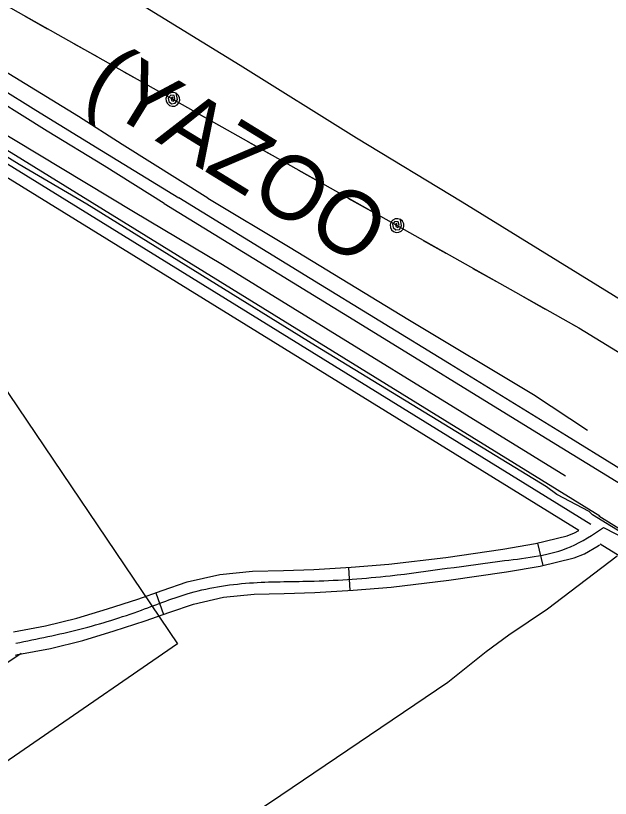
# Model space of a CAD drawing. Extents: x 3355724 to 3393621, y 594744 to 620174.
# Drawn here: x 3386643 to 3387415, y 614246 to 615262 of the extents above; entities that cross this region are included whole.
import ezdxf

# ---------------------------------------------------------------- set-up
doc = ezdxf.new("R2010")
doc.units = 0
for name, color, linetype in [('V-RAIL-IDEN', 7, 'Continuous'), ('V-RAIL-TRAK', 7, 'Continuous'), ('V-ROAD-CNTR', 7, 'Continuous'), ('V-SITE-OTLN', 7, 'Continuous'), ('V-TOPO-SHOR', 7, 'Continuous'), ('V-UTIL-LINE', 7, 'Continuous')]:
    doc.layers.add(name, color=color, linetype=linetype)

msp = doc.modelspace()

# ---------------------------------------------------------------- linework, layer by layer
at = {"layer": 'V-RAIL-TRAK'}
for points in [[(3385904.3, 615614.3), (3385937.1, 615589.8), (3385995.9, 615553.5), (3386041.4, 615526), (3386138.6, 615465.8), (3386217.5, 615417.8), (3386284.6, 615376.6), (3386346.6, 615338.2), (3386401.2, 615305), (3386480.6, 615255.4), (3386574.3, 615198.6), (3386668.9, 615139.7), (3386754.1, 615087.1), (3386854.6, 615025.9)], [(3386835.4, 615018.6), (3386757.4, 615067.4), (3386683.6, 615112.5), (3386589.3, 615171.1), (3386503.9, 615224.1), (3386434.9, 615265.6), (3386347.8, 615319.3), (3386239.7, 615386.2), (3386125.4, 615456), (3386093.2, 615476), (3386043.7, 615506.3), (3385985.4, 615542.7), (3385911.1, 615588.8), (3385897.3, 615598.6)], [(3387486.9, 614636.8), (3387357.9, 614716.6), (3387205.7, 614810.2), (3387025.1, 614921.2), (3386854.6, 615025.9)], [(3386835.4, 615018.6), (3387087.4, 614863.9), (3387313.5, 614724.5), (3387544.4, 614583), (3387825.6, 614410.3), (3388103.4, 614239), (3388374.3, 614072.6), (3388614, 613924.9), (3388857.9, 613775.8), (3389039.2, 613663.6), (3389053.7, 613654.6), (3389095.5, 613628.7), (3389291.1, 613509.4), (3389490.1, 613386), (3389587.1, 613326.5), (3389784.2, 613205.7), (3390000.1, 613072.5), (3390330.9, 612870), (3390414.6, 612817.9), (3390427.8, 612809.7), (3390622.7, 612689.7), (3390866.5, 612539.9), (3391139.5, 612371.4), (3391416.1, 612201.7)]]:
    msp.add_lwpolyline(points, dxfattribs=at)
at = {"layer": 'V-ROAD-CNTR'}
for p, q in [((3387399.6, 614612.9), (3387465.5, 614571.7)), ((3387320, 614577.3), (3387327.2, 614548.2)), ((3387401.5, 614576.3), (3387468.1, 614534.8)), ((3387074.8, 614545.8), (3387076.7, 614515.9)), ((3386824.5, 614512.8), (3386834.5, 614484.5))]:
    msp.add_line(p, q, dxfattribs=at)
for points in [[(3387400.8, 614612.4), (3386575.2, 615121.9)], [(3387389.5, 614601.7), (3386567.3, 615109.2)], [(3387373.7, 614593.8), (3386559.5, 615096.4)], [(3387405.9, 614597.5), (3387468.2, 614565.5), (3387486.3, 614571), (3387577.8, 614629.5)], [(3386722.1, 614479.9), (3386761.8, 614491.9), (3386801.4, 614504.6), (3386832.8, 614515.7), (3386865.4, 614527), (3386907.6, 614536.6), (3386950.3, 614540.9), (3386990.4, 614541.9), (3387029.6, 614543), (3387078.4, 614546), (3387127.2, 614550), (3387201.2, 614558.8), (3387275, 614569.4), (3387317.4, 614576.7), (3387358.6, 614586.9), (3387368.2, 614590.6), (3387373.7, 614593.8)], [(3386730.1, 614451), (3386770.7, 614463.3), (3386811, 614476.2), (3386842.7, 614487.4), (3386873.6, 614498.1), (3386912.4, 614506.9), (3386952.2, 614510.9), (3386991.2, 614511.9), (3387031, 614513), (3387080.6, 614516.1), (3387130.2, 614520.1), (3387205.1, 614529), (3387279.7, 614539.8), (3387323.6, 614547.3), (3387367.7, 614558.3), (3387381.2, 614563.5), (3387399, 614573.7), (3387400.7, 614575)], [(3386639.8, 614462), (3386681.5, 614469.9), (3386722.1, 614479.9)], [(3386642.5, 614431.9), (3386645.6, 614432.6), (3386687.9, 614440.6), (3386730.1, 614451)]]:
    msp.add_lwpolyline(points, dxfattribs=at)
msp.add_spline([(3386642.7, 614447.3), (3386726.1, 614465.5), (3386806.2, 614490.4), (3386869.5, 614512.6), (3386951.3, 614525.9), (3387030.3, 614528), (3387128.7, 614535), (3387277.4, 614554.6), (3387363.1, 614572.6), (3387405.9, 614597.5)], degree=3, dxfattribs=at)
at = {"layer": 'V-SITE-OTLN'}
msp.add_lwpolyline([(3386099.9, 614144.6), (3385980.1, 614338.3), (3385974.9, 614355.9), (3385980.6, 614391), (3385990.7, 614457), (3385986.8, 614473.2), (3385924.2, 614565.6), (3385890.9, 614610.4), (3386036.2, 614703.5), (3386096, 614612.6), (3386153.2, 614660.6), (3386080, 614770.6), (3386100.4, 614786.6), (3386184.3, 614672.5), (3386257.7, 614729.8), (3386271, 614709.4), (3386362.1, 614782.8), (3386426.1, 614691.8), (3386605.3, 614811.6), (3386610.6, 614804.8), (3386852.9, 614446.3), (3386493, 614198.6)], dxfattribs=at)
at = {"layer": 'V-TOPO-SHOR'}
for points in [[(3386892.2, 615025.3), (3386781, 615095.3), (3386724.3, 615131.4), (3386619.9, 615195.1), (3386538, 615237.7), (3386497.1, 615264.6), (3386484.8, 615275.8)], [(3386424.9, 615231.5), (3386795.8, 615008), (3386911, 614939.3), (3387356.4, 614664.5)], [(3386892.2, 615025.3), (3386998.9, 614961.4), (3387151.9, 614868.3), (3387315.1, 614770.4), (3387385.1, 614723.9)], [(3385967.3, 613560.4), (3386153.7, 613686.7), (3386291.4, 613784.5), (3386295.5, 613787.3), (3386325.1, 613807.4), (3386350.6, 613829.1), (3386363, 613837.9), (3386374.7, 613843.2), (3386384.3, 613845.9), (3386392.5, 613849.2), (3386414.5, 613859.9), (3386466.1, 613893.6), (3386544.5, 613946.9), (3386649.1, 614021.2), (3386816.4, 614135.2), (3386987, 614249.8), (3387203.7, 614396.8), (3387253.3, 614436.7), (3387282.9, 614458.3), (3387333.2, 614492), (3387423.4, 614560.9)]]:
    msp.add_lwpolyline(points, dxfattribs=at)
at = {"layer": 'V-UTIL-LINE'}
for points in [[(3390862.5, 618393.4), (3386415.7, 615396.7), (3387373.6, 614856.8), (3390174.5, 613140.8)], [(3387222.5, 615020), (3387085.3, 615103.5), (3386934, 615197.9), (3386805.1, 615277), (3386658.1, 615367.7), (3386619.5, 615392.7), (3386592.7, 615374.8), (3386544.2, 615448.1)], [(3386734.9, 615017.5), (3386647.4, 615069.3), (3386534.2, 615138.7), (3386447, 615191.9), (3386341.5, 615256.7), (3386309.6, 615275.8), (3386263.7, 615245.6), (3386259.1, 615243.2), (3386191.2, 615195.5), (3386076.2, 615118.1), (3385967, 615049.1)], [(3386654.2, 615262.2), (3386683.8, 615245.5)], [(3386718.7, 615225.9), (3386748.3, 615209.2)], [(3386783.2, 615189.6), (3386812.8, 615172.9)], [(3386846.8, 615153.7), (3386846.5, 615156.6), (3386844.7, 615155.1), (3386845, 615152.4), (3386847.7, 615151.2), (3386849.5, 615154.1), (3386848.4, 615158.6), (3386844.1, 615159), (3386840.7, 615155.5), (3386841.7, 615151.1), (3386845, 615148.1), (3386849.8, 615148.9), (3386852.8, 615153.6), (3386851.2, 615161.6), (3386847.8, 615162.7), (3386844.3, 615162.4), (3386841.2, 615160.8), (3386838.9, 615158.1), (3386837.8, 615154.8), (3386838.1, 615151.3), (3386839.7, 615148.2), (3386842.3, 615145.9), (3386845.7, 615144.8), (3386849.2, 615145.1), (3386852.3, 615146.6), (3386854.6, 615149.3), (3386855.7, 615152.6), (3386855.4, 615156.1), (3386853.8, 615159.3), (3386851.2, 615161.6)], [(3386880.7, 615134.6), (3386910.3, 615117.9)], [(3386945.2, 615098.2), (3386974.8, 615081.5)], [(3387009.7, 615061.9), (3387039.3, 615045.2)], [(3387074.1, 615025.6), (3387103.7, 615008.9)], [(3387619.7, 613620.6), (3387898.4, 613808.6), (3388151.7, 613978.9), (3388141.9, 613993.6), (3388250.8, 614068.3), (3388237.1, 614093), (3388070.1, 614200.1), (3387723.4, 614409.9), (3387391.3, 614614.2), (3387387.3, 614618.2), (3387345, 614640.6), (3387331.8, 614650.6), (3387032.1, 614833.4), (3386734.9, 615017.5)], [(3388429.1, 614277.4), (3388165.3, 614438.8), (3387841.8, 614637.6), (3387721, 614713.1), (3387647.1, 614758.1), (3387470.8, 614866.9), (3387222.5, 615020)], [(3387137.7, 614989.7), (3387137.5, 614992.6), (3387135.7, 614991.1), (3387136, 614988.4), (3387138.7, 614987.2), (3387140.5, 614990.1), (3387139.4, 614994.6), (3387135.1, 614995), (3387131.7, 614991.5), (3387132.7, 614987.1), (3387136, 614984.1), (3387140.8, 614984.9), (3387143.7, 614989.6), (3387142.1, 614997.6), (3387138.8, 614998.7), (3387135.3, 614998.4), (3387132.2, 614996.8), (3387129.9, 614994.2), (3387128.8, 614990.8), (3387129.1, 614987.3), (3387130.6, 614984.2), (3387133.3, 614981.9), (3387136.6, 614980.8), (3387140.1, 614981.1), (3387143.3, 614982.6), (3387145.6, 614985.3), (3387146.7, 614988.6), (3387146.4, 614992.2), (3387144.8, 614995.3), (3387142.1, 614997.6)], [(3387171.7, 614970.6), (3387201.3, 614953.9)], [(3387236.2, 614934.2), (3387265.8, 614917.6)], [(3387300.6, 614897.9), (3387330.2, 614881.2)], [(3387365.1, 614861.6), (3387373.6, 614856.8)], [(3387373.6, 614856.8), (3387402.6, 614839)], [(3386607.7, 614405), (3386620.4, 614414.9), (3386649.8, 614434.5)]]:
    msp.add_lwpolyline(points, dxfattribs=at)

# ---------------------------------------------------------------- texts
at = {"layer": 'V-RAIL-IDEN'}
msp.add_text('(YAZOO', height=83, rotation=328.3925, dxfattribs=at).set_placement((3386728.3, 615158.7))

doc.saveas('drawing.dxf')
